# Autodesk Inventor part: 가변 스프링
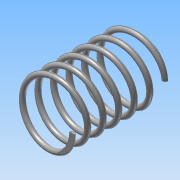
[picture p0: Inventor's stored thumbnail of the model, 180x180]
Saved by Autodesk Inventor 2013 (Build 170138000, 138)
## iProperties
Created: 2018-06
Part Number: 가변 스프링
Material: 강철, 연강
Document SubType Name: Modeling
Designer: Administrator
Density: 7.86 g/cm^3
Mass: 82.8128 g
Surface Area: 106.474 cm^2
Volume: 10.536 cm^3
Author: Administrator
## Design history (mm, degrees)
sketch "스케치1"
  geometry: L1 (0, 0)-(0, 73.25); L2 (0, 73.25)-(22.5, 73.25); L3 (0, 0)-(22.5, 0); C1 r 2 at (22.5, 0)
  constraints: 6 end point, 2 parallel, 1 centre point, 1 coincident, 1 perpendicular, 1 vertical
  dimensions: "d0" = 73.25 distance of L1.start L1.end (derived); "d1" = 45 diameter of L2.end L1; "d2" = 4 diameter of C1
feature "코일1" sketch "스케치1" pitch "d3" = 10; turns "d5" = 6; dims "d4" = 73.25 (= d0), "d6" = 0, angle "d7" = 90 deg, angle "d8" = 90 deg, "d9" = 0, "d10" = 0
sketch "스케치2"
  geometry: L1 (73.25, 24.5)-(0, 24.5); L2 (0, 24.5)-(0, -24.5); L3 (0, -24.5)-(73.25, -24.5); L4 (73.25, -24.5)-(73.25, 24.5); 2 further points
  constraints: 8 end point, 2 parallel, 1 coincident, 1 horizontal, 1 midpoint, 1 perpendicular
  dimensions: "d11" = 73.25 distance of L3.end L2.end (derived); "d12" = 49 distance of L2.end L1.end
extrude "돌출1" sketch "스케치2" stored distance "d13" = 50; taper "d14" = 0 deg
node "솔리드1"
